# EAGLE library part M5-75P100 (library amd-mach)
AMD MACH SERIES
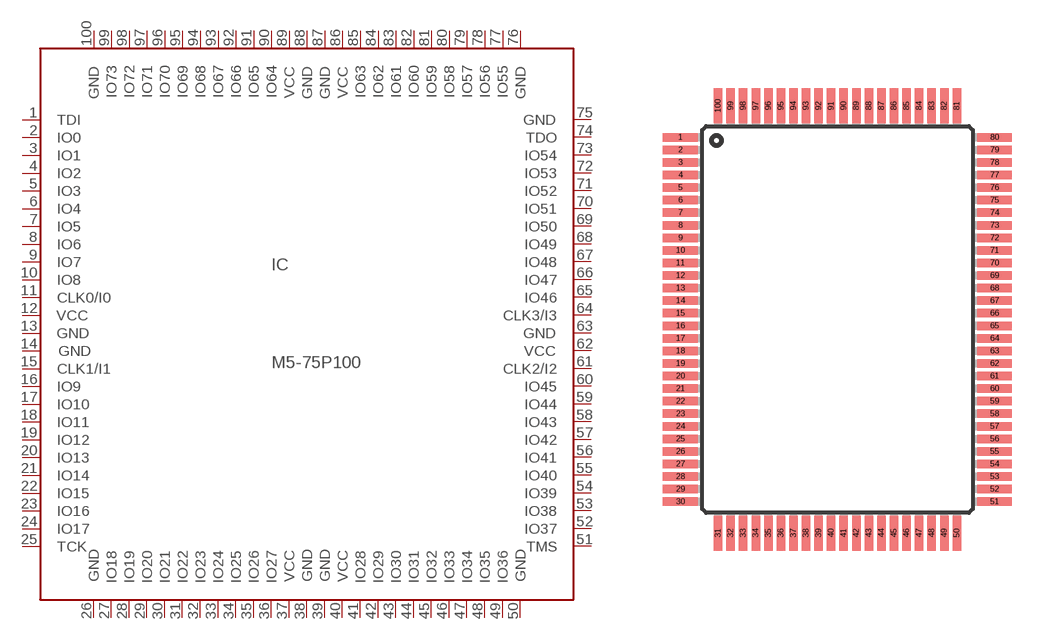
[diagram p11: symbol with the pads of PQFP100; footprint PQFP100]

Designator prefix IC

## M5-75P100 (OC_FARNELL: unknown; OC_NEWARK: unknown)  [PQFP100]
1  TDI  in
2  IO0
3  IO1
4  IO2
5  IO3
6  IO4
7  IO5
8  IO6
9  IO7
10  IO8
11  CLK0/I0  in
12  VCC  pwr
13  GND  pwr
14  GND  pwr
15  CLK1/I1  in
16  IO9
17  IO10
18  IO11
19  IO12
20  IO13
21  IO14
22  IO15
23  IO16
24  IO17
25  TCK  in
26  GND  pwr
27  IO18
28  IO19
29  IO20
30  IO21
31  IO22
32  IO23
33  IO24
34  IO25
35  IO26
36  IO27
37  VCC  pwr
38  GND  pwr
39  GND  pwr
40  VCC  pwr
41  IO28
42  IO29
43  IO30
44  IO31
45  IO32
46  IO33
47  IO34
48  IO35
49  IO36
50  GND  pwr
51  TMS  in
52  IO37
53  IO38
54  IO39
55  IO40
56  IO41
57  IO42
58  IO43
59  IO44
60  IO45
61  CLK2/I2  in
62  VCC  pwr
63  GND  pwr
64  CLK3/I3  in
65  IO46
66  IO47
67  IO48
68  IO49
69  IO50
70  IO51
71  IO52
72  IO53
73  IO54
74  TDO  out
75  GND  pwr
76  GND  pwr
77  IO55
78  IO56
79  IO57
80  IO58
81  IO59
82  IO60
83  IO61
84  IO62
85  IO63
86  VCC  pwr
87  GND  pwr
88  GND  pwr
89  VCC  pwr
90  IO64
91  IO65
92  IO66
93  IO67
94  IO68
95  IO69
96  IO70
97  IO71
98  IO72
99  IO73
100  GND  pwr

## Footprint PQFP100 (pad centres in mm)
PLASTIC QUAD FLAT PACK
smd 1.8 x 0.44: 1 -8.125,9.425; 2 -8.125,8.775; 3 -8.125,8.125; 4 -8.125,7.475; 5 -8.125,6.825; 6 -8.125,6.175; 7 -8.125,5.525; 8 -8.125,4.875; 9 -8.125,4.225; 10 -8.125,3.575; 11 -8.125,2.925; 12 -8.125,2.275; 13 -8.125,1.625; 14 -8.125,0.975; 15 -8.125,0.325; 16 -8.125,-0.325; 17 -8.125,-0.975; 18 -8.125,-1.625; 19 -8.125,-2.275; 20 -8.125,-2.925; 21 -8.125,-3.575; 22 -8.125,-4.225; 23 -8.125,-4.875; 24 -8.125,-5.525; 25 -8.125,-6.175; 26 -8.125,-6.825; 27 -8.125,-7.475; 28 -8.125,-8.125; 29 -8.125,-8.775; 30 -8.125,-9.425; 51 8.125,-9.425; 52 8.125,-8.775; 53 8.125,-8.125; 54 8.125,-7.475; 55 8.125,-6.825; 56 8.125,-6.175; 57 8.125,-5.525; 58 8.125,-4.875; 59 8.125,-4.225; 60 8.125,-3.575; 61 8.125,-2.925; 62 8.125,-2.275; 63 8.125,-1.625; 64 8.125,-0.975; 65 8.125,-0.325; 66 8.125,0.325; 67 8.125,0.975; 68 8.125,1.625; 69 8.125,2.275; 70 8.125,2.925; 71 8.125,3.575; 72 8.125,4.225; 73 8.125,4.875; 74 8.125,5.525; 75 8.125,6.175; 76 8.125,6.825; 77 8.125,7.475; 78 8.125,8.125; 79 8.125,8.775; 80 8.125,9.425
smd 0.44 x 1.8: 31 -6.175,-11.05; 32 -5.525,-11.05; 33 -4.875,-11.05; 34 -4.225,-11.05; 35 -3.575,-11.05; 36 -2.925,-11.05; 37 -2.275,-11.05; 38 -1.625,-11.05; 39 -0.975,-11.05; 40 -0.325,-11.05; 41 0.325,-11.05; 42 0.975,-11.05; 43 1.625,-11.05; 44 2.275,-11.05; 45 2.925,-11.05; 46 3.575,-11.05; 47 4.225,-11.05; 48 4.875,-11.05; 49 5.525,-11.05; 50 6.175,-11.05; 81 6.175,11.05; 82 5.525,11.05; 83 4.875,11.05; 84 4.225,11.05; 85 3.575,11.05; 86 2.925,11.05; 87 2.275,11.05; 88 1.625,11.05; 89 0.975,11.05; 90 0.325,11.05; 91 -0.325,11.05; 92 -0.975,11.05; 93 -1.625,11.05; 94 -2.275,11.05; 95 -2.925,11.05; 96 -3.575,11.05; 97 -4.225,11.05; 98 -4.875,11.05; 99 -5.525,11.05; 100 -6.175,11.05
